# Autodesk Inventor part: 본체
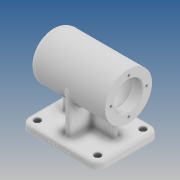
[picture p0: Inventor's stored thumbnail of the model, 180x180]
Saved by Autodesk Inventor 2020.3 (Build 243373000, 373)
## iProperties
Created: 2020-10
Part Number: 본체
Material: 알루미늄 6061
Document SubType Name: Modeling
Designer: EZDESIGN
Mass: 1026.28 g
Surface Area: 757.984 cm^2
Volume: 380.103 cm^3
Density: 2.7 g/cm^3
Appearance: 기본값
Author: EZDESIGN
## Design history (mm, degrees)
sketch "스케치1"
  geometry: L1 (56, 45)-(-56, 45); L2 (-56, 45)-(-56, -45); L3 (-56, -45)-(56, -45); L4 (56, -45)-(56, 45); L5 (56, 45)-(-56, -45); L6 (-56, 45)-(56, -45); 1 further point
  constraints: 12 end point, 2 midpoint, 2 parallel, 1 horizontal, 1 perpendicular
  dimensions: "d0" = 112 distance of L3.end L2.end; "d1" = 90 distance of L2.end L1.end
extrude "돌출1" new body sketch "스케치1" distance "d2" = 10; taper "d3" = 0 deg
sketch "스케치2"
  geometry: L1 (-56, 74)-(73.911, 74); L2 (-56, 74)-(-56, 98); L3 (-46, 108)-(56, 108); L4 (56, 108)-(56, 95); L5 (56, 95)-(41, 95); L6 (41, 95)-(41, 95); L7 (38, 98)-(-10, 98); L8 (-25, 91.5)-(-42.7, 91.5); L9 (-43, 91.2)-(-43, 90); L10 (-43, 90)-(-46.7, 90); L11 (-47, 89.7)-(-47, 84.5); L12 (-47, 84.5)-(-47, 84.5); L13 (-50, 81.5)-(-50, 74); L14 (-25, 91.5)-(-25, 94.7); L15 (-24.7, 95)-(-13, 95); L16 (-13, 95)-(-13, 95); L17 (56, 0)-(56, 10) reference; A1 r 10 centre (-46, 98) between (-46, 108) and (-56, 98); A2 r 3 centre (-47, 81.5) between (-47, 84.5) and (-50, 81.5); A3 r 3 centre (-10, 95) between (-10, 98) and (-13, 95); A4 r 3 centre (38, 95) between (41, 95) and (38, 98); A5 r 0.3 centre (-46.7, 89.7) between (-46.7, 90) and (-47, 89.7); A6 r 0.3 centre (-42.7, 91.2) between (-42.7, 91.5) and (-43, 91.2); A7 r 0.3 centre (-24.7, 94.7) between (-24.7, 95) and (-25, 94.7); 10 further points
  constraints: 32 end point, 14 point on circle, 14 tangent, 13 point on line, 12 perpendicular, 7 centre point, 4 equal radius, 2 vertical, 1 collinear, 1 horizontal
  dimensions: "d4" = 74 distance from line of L1 point (0, 0); "d5" = 21 diameter of L12 L1; "d6" = 32 diameter of L10 L1; "d7" = 35 diameter of L8 L1; "d8" = 42 diameter of L15 L1; "d9" = 48 diameter of L7 L1; "d10" = 42 diameter of L5 L1; "d11" = 68 diameter of L3 L1; "d12" = 15 distance of L4.end L5.end; "d13" = 54 distance of point (41, 98) point (-13, 98); "d14" = 12 distance of point (-25, 95) L15.end; "d15" = 18 distance of L8.start point (-43, 91.5); "d16" = 4 distance of L9.end point (-47, 90); "d17" = 3 distance of L11.end point (-50, 84.5); "d18" = 112 distance between parallel lines of L4 L2; "d19" = 10 radius of A1; "d20" = 3 radius of A2; "d21" = 0.3 radius of A5
revolve "회전1" sketch "스케치2" stored, may be unused: angle "d22" = 90 deg
sketch "스케치3"
  geometry: L1 (-4, 4)-(-4, 34); L2 (-4, 34)-(4, 34); L3 (4, 34)-(4, 4); L4 (4, 4)-(38, 4); L5 (38, 4)-(38, -4); L6 (38, -4)-(4, -4); L7 (4, -4)-(4, -34); L8 (4, -34)-(-4, -34); L9 (-4, -34)-(-4, -4); L10 (-38, -4)-(-38, 4); L11 (-38, 4)-(-4, 4); L12 (-38, -4)-(-4, -4); L13 (56, -45)-(56, 45) reference; L14 (-56, 45)-(-56, -45) reference; 3 further points
  constraints: 24 end point, 7 perpendicular, 7 point on line, 2 midpoint, 2 parallel, 1 horizontal alignment, 1 vertical, 1 vertical alignment
  dimensions: "d23" = 8 distance between parallel lines of L1 L3; "d24" = 8 distance between parallel lines of L6 L4; "d25" = 18 distance between parallel lines of L13 L5; "d26" = 18 distance between parallel lines of L14 L10; "d27" = 68 distance from line of L7.end L2; "d28" = 34 distance from line of L2 point (0, 0)
extrude "돌출2" join sketch "스케치3" stored distance "d29" = 10; taper "d30" = 0 deg
fillet "모깎기1" dims "d31" = 12
sketch "스케치4"
  geometry: A1 r 12 centre (-44, 33) between (-44, 45) and (-56, 33) reference; A2 r 12 centre (44, 33) between (56, 33) and (44, 45) reference; A3 r 12 centre (44, -33) between (44, -45) and (56, -33) reference; A4 r 12 centre (-44, -33) between (-56, -33) and (-44, -45) reference; 5 further points
  constraints: 4 coincident
hole "구멍1" sketch "스케치4" at (-44, 33), (44, 33), (44, -33), (-44, -33) diameter "d32" = 5.5; stored, may be unused: countersink angle "d36" = 90 deg, drill point angle "d38" = 118 deg; dims "d33" = 6, "d34" = 9.5, "d35" = 5.4, "d37" = 8
sketch "스케치5" dims "d39" = 52
  geometry: L1 (0, 0)-(0, 41.994); C1 r 34 at (0, 0) reference; 2 further points
  constraints: 2 end point, 1 coincident, 1 point on line, 1 vertical, 1 vertical alignment, 2 other
hole "구멍2" sketch "스케치5" at (0, 26) diameter "d40" = 3.242; stored, may be unused: countersink angle "d44" = 90 deg, drill point angle "d46" = 118 deg; dims "d41" = 8, "d42" = 9.5, "d43" = 5.4, "d45" = 11
chamfer "모따기1" distance "d50" = 1; stored, may be unused: second distance "d51" = 2, angle "d52" = 45 deg
fillet "모깎기2" dims "d53" = 3
fillet "모깎기3" dims "d54" = 3
sketch "스케치6"
  geometry: L1 (100, 0)-(100, 7) reference; L2 (0, 0)-(88, 0) reference; 2 further points
  constraints: 1 other
  dimensions: "d55" = 56 distance from line of L1 point (44, 3); "d56" = 3 distance from line of L2 point (44, 3)
feature "엠보싱1" sketch "스케치6" dims "d0" = 112, "d1" = 90, "d13" = 54, "d57" = 0.5, "d58" = 0
node "솔리드1"
pattern_circular "원형 패턴1" dims angle "d48" = 360 deg
feature "A9D066F2-1C7D-4E18-AEED-F7BC21143FA4" dims "d40" = 3.242, "d41" = 8, "d42" = 9.5, "d43" = 5.4, "d44" = 90 deg, "d45" = 11, "d46" = 118 deg
